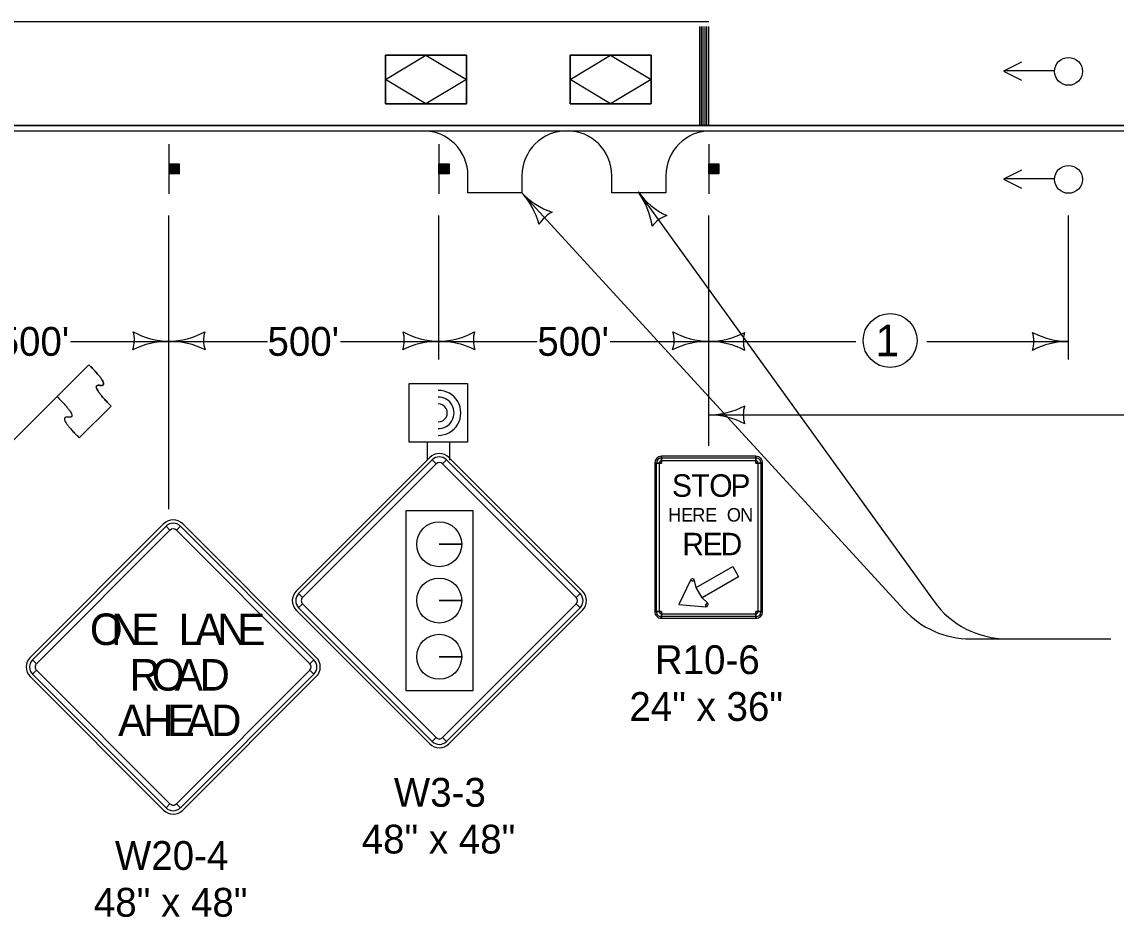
# Model space of a CAD drawing. Extents: x -2134934 to -2127057, y -2139046 to -2137036.
# Drawn here: x -2134616 to -2134008, y -2138105 to -2137608 of the extents above; entities that cross this region are included whole.
import ezdxf

# ---------------------------------------------------------------- set-up
doc = ezdxf.new("R2010")
doc.units = 0
for name, color, linetype in [('Barrier', 7, 'Continuous'), ('BridgeSuperStructureExisting', 7, 'Continuous'), ('DsnShtPlotIdentification', 7, 'Continuous'), ('DsnShtPlotShape', 7, 'Continuous'), ('dsnTextFinalPlan', 7, 'Continuous'), ('TC_Barrier', 7, 'Continuous')]:
    doc.layers.add(name, color=color, linetype=linetype)

msp = doc.modelspace()

# ---------------------------------------------------------------- linework, layer by layer
at = {"layer": 'Barrier'}
for p, q in [((-2134636.31, -2137855.42), (-2134578.99, -2137798.11)), ((-2134578.99, -2137798.11), (-2134596.67, -2137815.79)), ((-2134584.29, -2137838.78), (-2134566.61, -2137821.1)), ((-2134389.44, -2137849.65), (-2134463.68, -2137923.9)), ((-2134388.11, -2137850.98), (-2134385.9, -2137853.19)), ((-2134382.37, -2137853.19), (-2134380.16, -2137850.98)), ((-2134304.59, -2137923.9), (-2134378.83, -2137849.65)), ((-2134264.44, -2137852.75), (-2134260.69, -2137852.75)), ((-2134263.5, -2137852.75), (-2134261.94, -2137852.75)), ((-2134260.69, -2137852.75), (-2134260.69, -2137849)), ((-2134260.69, -2137851.5), (-2134260.69, -2137849.93)), ((-2134208.19, -2137849), (-2134208.19, -2137852.75)), ((-2134208.19, -2137849.93), (-2134208.19, -2137851.5)), ((-2134208.19, -2137852.75), (-2134204.44, -2137852.75)), ((-2134206.94, -2137852.75), (-2134205.38, -2137852.75)), ((-2134537.4, -2137886.48), (-2134611.65, -2137960.72)), ((-2134536.08, -2137887.8), (-2134533.87, -2137890.01)), ((-2134530.33, -2137890.01), (-2134528.12, -2137887.8)), ((-2134452.55, -2137960.72), (-2134526.8, -2137886.48)), ((-2134371.73, -2137897.87), (-2134384.23, -2137897.87)), ((-2134384.23, -2137897.87), (-2134371.73, -2137897.87)), ((-2134244.58, -2137917.73), (-2134243.48, -2137918.31)), ((-2134243.48, -2137918.31), (-2134242.26, -2137918.04)), ((-2134460.15, -2137927.43), (-2134462.36, -2137925.22)), ((-2134305.91, -2137925.22), (-2134308.12, -2137927.43)), ((-2134462.36, -2137933.18), (-2134460.15, -2137930.97)), ((-2134371.73, -2137929.12), (-2134384.23, -2137929.12)), ((-2134384.23, -2137929.12), (-2134371.73, -2137929.12)), ((-2134308.12, -2137930.97), (-2134305.91, -2137933.18)), ((-2134235.98, -2137931.3), (-2134236.03, -2137932.55)), ((-2134235.13, -2137930.38), (-2134235.98, -2137931.3)), ((-2134463.68, -2137934.5), (-2134389.44, -2138008.75)), ((-2134378.83, -2138008.75), (-2134304.59, -2137934.5)), ((-2134260.69, -2137935.24), (-2134264.44, -2137935.24)), ((-2134261.94, -2137935.24), (-2134263.5, -2137935.24)), ((-2134260.69, -2137938.99), (-2134260.69, -2137935.24)), ((-2134260.69, -2137938.06), (-2134260.69, -2137936.49)), ((-2134204.44, -2137935.24), (-2134208.19, -2137935.24)), ((-2134208.19, -2137935.24), (-2134208.19, -2137938.99)), ((-2134208.19, -2137936.49), (-2134208.19, -2137938.06)), ((-2134205.38, -2137935.24), (-2134206.94, -2137935.24)), ((-2134608.11, -2137964.26), (-2134610.32, -2137962.05)), ((-2134453.88, -2137962.05), (-2134456.08, -2137964.26)), ((-2134371.73, -2137960.37), (-2134384.23, -2137960.37)), ((-2134384.23, -2137960.37), (-2134371.73, -2137960.37)), ((-2134610.32, -2137970.01), (-2134608.11, -2137967.8)), ((-2134456.08, -2137967.8), (-2134453.88, -2137970.01)), ((-2134611.65, -2137971.33), (-2134537.4, -2138045.58)), ((-2134526.8, -2138045.58), (-2134452.55, -2137971.33)), ((-2134385.9, -2138005.21), (-2134388.11, -2138007.42)), ((-2134380.16, -2138007.42), (-2134382.37, -2138005.21)), ((-2134533.87, -2138042.04), (-2134536.08, -2138044.25)), ((-2134528.12, -2138044.25), (-2134530.33, -2138042.04))]:
    msp.add_line(p, q, dxfattribs=at)
for points in [[(-2134388.11, -2137850.98), (-2134462.36, -2137925.22), (-2134460.15, -2137927.43), (-2134385.9, -2137853.19), (-2134388.11, -2137850.98)], [(-2134305.91, -2137925.22), (-2134380.16, -2137850.98), (-2134382.37, -2137853.19), (-2134308.12, -2137927.43), (-2134305.91, -2137925.22)], [(-2134260.69, -2137938.99), (-2134208.19, -2137938.99), (-2134208.19, -2137935.24), (-2134204.44, -2137935.24), (-2134204.44, -2137852.75), (-2134208.19, -2137852.75), (-2134208.19, -2137849), (-2134260.69, -2137849), (-2134260.69, -2137852.75), (-2134264.44, -2137852.75), (-2134264.44, -2137935.24), (-2134260.69, -2137935.24), (-2134260.69, -2137938.99)], [(-2134261.94, -2137852.75), (-2134261.94, -2137935.24), (-2134263.5, -2137935.24), (-2134263.5, -2137852.75), (-2134261.94, -2137852.75)], [(-2134208.19, -2137851.5), (-2134260.69, -2137851.5), (-2134260.69, -2137849.93), (-2134208.19, -2137849.93), (-2134208.19, -2137851.5)], [(-2134206.94, -2137935.24), (-2134206.94, -2137852.75), (-2134205.38, -2137852.75), (-2134205.38, -2137935.24), (-2134206.94, -2137935.24)], [(-2134365.4, -2137879.26), (-2134402.87, -2137879.26), (-2134402.87, -2137979.15), (-2134365.4, -2137979.15), (-2134365.4, -2137879.26)], [(-2134536.08, -2137887.8), (-2134610.32, -2137962.05), (-2134608.11, -2137964.26), (-2134533.87, -2137890.01), (-2134536.08, -2137887.8)], [(-2134453.88, -2137962.05), (-2134528.12, -2137887.8), (-2134530.33, -2137890.01), (-2134456.08, -2137964.26), (-2134453.88, -2137962.05)], [(-2134221.07, -2137910.24), (-2134217.79, -2137915.93), (-2134238.1, -2137927.65), (-2134241.38, -2137921.97), (-2134221.07, -2137910.24)], [(-2134251.09, -2137931.37), (-2134236.03, -2137932.55), (-2134235.98, -2137931.3), (-2134235.13, -2137930.38), (-2134238.1, -2137927.65), (-2134241.38, -2137921.97), (-2134242.26, -2137918.04), (-2134243.48, -2137918.31), (-2134244.58, -2137917.73), (-2134251.09, -2137931.37)], [(-2134462.36, -2137933.18), (-2134388.11, -2138007.42), (-2134385.9, -2138005.21), (-2134460.15, -2137930.97), (-2134462.36, -2137933.18)], [(-2134380.16, -2138007.42), (-2134305.91, -2137933.18), (-2134308.12, -2137930.97), (-2134382.37, -2138005.21), (-2134380.16, -2138007.42)], [(-2134260.69, -2137936.49), (-2134208.19, -2137936.49), (-2134208.19, -2137938.06), (-2134260.69, -2137938.06), (-2134260.69, -2137936.49)], [(-2134610.32, -2137970.01), (-2134536.08, -2138044.25), (-2134533.87, -2138042.04), (-2134608.11, -2137967.8), (-2134610.32, -2137970.01)], [(-2134528.12, -2138044.25), (-2134453.88, -2137970.01), (-2134456.08, -2137967.8), (-2134530.33, -2138042.04), (-2134528.12, -2138044.25)]]:
    msp.add_lwpolyline(points, close=True, dxfattribs=at)
for centre in [(-2134384.23, -2137897.87), (-2134384.23, -2137929.12), (-2134384.23, -2137960.37)]:
    msp.add_circle(centre, 12.5, dxfattribs=at)
for centre, radius, start, end in [((-2134384.14, -2137854.96), 7.5, 44.99999, 134.99974), ((-2134384.14, -2137854.96), 5.62, 44.99999, 134.99974), ((-2134384.14, -2137854.96), 2.5, 44.99999, 134.99974), ((-2134260.69, -2137852.75), 3.75, 90.00021, 179.99985), ((-2134260.69, -2137852.75), 2.81, 90.00021, 179.99985), ((-2134260.69, -2137852.75), 1.25, 90.00021, 179.99985), ((-2134208.19, -2137852.75), 3.75, 0, 90.00021), ((-2134208.19, -2137852.75), 2.81, 0, 90.00021), ((-2134208.19, -2137852.75), 1.25, 0, 90.00021), ((-2134532.1, -2137891.78), 7.5, 44.99999, 134.99974), ((-2134532.1, -2137891.78), 5.62, 44.99999, 134.99974), ((-2134532.1, -2137891.78), 2.5, 44.99999, 134.99974), ((-2134243.48, -2137918.31), 1.25, 12.62232, 152.27557), ((-2134458.38, -2137929.2), 7.5, 134.99974, 224.99995), ((-2134458.38, -2137929.2), 5.62, 134.99974, 224.99995), ((-2134309.89, -2137929.2), 5.62, 315.00016, 44.9998), ((-2134309.89, -2137929.2), 7.5, 315.00016, 44.9998), ((-2134458.38, -2137929.2), 2.5, 134.99974, 224.99995), ((-2134309.89, -2137929.2), 2.5, 315.00016, 44.9998), ((-2134235.98, -2137931.3), 1.25, 267.72427, 47.37758), ((-2134260.69, -2137935.24), 3.75, 179.99985, 270.00006), ((-2134260.69, -2137935.24), 2.81, 179.99985, 270.00006), ((-2134260.69, -2137935.24), 1.25, 179.99985, 270.00006), ((-2134208.19, -2137935.24), 3.75, 270.00006, 0.00027), ((-2134208.19, -2137935.24), 2.81, 270.00006, 0.00027), ((-2134208.19, -2137935.24), 1.25, 270.00006, 0.00027), ((-2134606.34, -2137966.03), 7.5, 134.99974, 224.99995), ((-2134606.34, -2137966.03), 5.62, 134.99974, 224.99995), ((-2134457.85, -2137966.03), 5.62, 315.00016, 44.9998), ((-2134457.85, -2137966.03), 7.5, 315.00016, 44.9998), ((-2134606.34, -2137966.03), 2.5, 134.99974, 224.99995), ((-2134457.85, -2137966.03), 2.5, 315.00016, 44.9998), ((-2134384.14, -2138003.45), 7.5, 224.99995, 315.00016), ((-2134384.14, -2138003.45), 5.62, 224.99995, 315.00016), ((-2134384.14, -2138003.45), 2.5, 224.99995, 315.00016), ((-2134532.1, -2138040.27), 7.5, 224.99995, 315.00016), ((-2134532.1, -2138040.27), 5.62, 224.99995, 315.00016), ((-2134532.1, -2138040.27), 2.5, 224.99995, 315.00016)]:
    msp.add_arc(centre, radius, start, end, dxfattribs=at)
for points in [[(-2134566.61, -2137821.1), (-2134578.99, -2137808.72), (-2134566.61, -2137810.49), (-2134578.99, -2137798.11)], [(-2134596.67, -2137815.79), (-2134584.29, -2137828.17), (-2134596.66, -2137826.4), (-2134584.29, -2137838.78)]]:
    msp.add_open_spline(points, degree=2, dxfattribs=at)
at = {"layer": 'BridgeSuperStructureExisting'}
for p, q in [((-2134239.44, -2137665.16), (-2134239.44, -2137610.16)), ((-2134238.44, -2137665.16), (-2134238.44, -2137610.16)), ((-2134237.44, -2137665.16), (-2134237.44, -2137610.16)), ((-2134236.44, -2137665.16), (-2134236.44, -2137610.16)), ((-2134235.44, -2137665.16), (-2134235.44, -2137610.16)), ((-2134234.44, -2137665.16), (-2134234.44, -2137610.16)), ((-2134414.12, -2137653.13), (-2134414.12, -2137626.13)), ((-2134414.12, -2137626.13), (-2134369.12, -2137626.13)), ((-2134414.12, -2137653.13), (-2134414.12, -2137626.13)), ((-2134414.12, -2137626.13), (-2134369.12, -2137626.13)), ((-2134369.12, -2137626.13), (-2134414.12, -2137626.13)), ((-2134414.12, -2137626.13), (-2134414.12, -2137653.13)), ((-2134369.12, -2137653.13), (-2134369.12, -2137626.13)), ((-2134369.12, -2137626.13), (-2134369.12, -2137653.13)), ((-2134369.12, -2137653.13), (-2134369.12, -2137626.13)), ((-2134311.44, -2137653.13), (-2134311.44, -2137626.13)), ((-2134311.44, -2137626.13), (-2134266.44, -2137626.13)), ((-2134311.44, -2137653.13), (-2134311.44, -2137626.13)), ((-2134311.44, -2137626.13), (-2134266.44, -2137626.13)), ((-2134266.44, -2137626.13), (-2134311.44, -2137626.13)), ((-2134311.44, -2137626.13), (-2134311.44, -2137653.13)), ((-2134266.44, -2137653.13), (-2134266.44, -2137626.13)), ((-2134266.44, -2137626.13), (-2134266.44, -2137653.13)), ((-2134266.44, -2137653.13), (-2134266.44, -2137626.13)), ((-2134042.18, -2137634.79), (-2134070.12, -2137634.79)), ((-2134414.12, -2137653.13), (-2134369.12, -2137653.13)), ((-2134369.12, -2137653.13), (-2134414.12, -2137653.13)), ((-2134414.12, -2137653.13), (-2134369.12, -2137653.13)), ((-2134311.44, -2137653.13), (-2134266.44, -2137653.13)), ((-2134266.44, -2137653.13), (-2134311.44, -2137653.13)), ((-2134311.44, -2137653.13), (-2134266.44, -2137653.13)), ((-2134884.44, -2137665.16), (-2133384.44, -2137665.16)), ((-2134393.26, -2137668.16), (-2134313.26, -2137668.16)), ((-2134313.26, -2137668.16), (-2134233.26, -2137668.16)), ((-2134534.44, -2137675.66), (-2134534.44, -2137703.16)), ((-2134384.44, -2137675.66), (-2134384.44, -2137703.16)), ((-2134234.44, -2137675.66), (-2134234.44, -2137703.16)), ((-2134534.03, -2137692.11), (-2134534.03, -2137686.52)), ((-2134533.75, -2137686.52), (-2134533.75, -2137692.11)), ((-2134533.48, -2137692.11), (-2134533.48, -2137686.52)), ((-2134533.22, -2137686.52), (-2134533.22, -2137692.11)), ((-2134533, -2137692.11), (-2134533, -2137686.52)), ((-2134532.79, -2137686.52), (-2134532.79, -2137692.11)), ((-2134532.45, -2137692.11), (-2134532.45, -2137686.52)), ((-2134532.19, -2137686.52), (-2134532.19, -2137692.11)), ((-2134531.97, -2137692.11), (-2134531.98, -2137686.52)), ((-2134531.65, -2137686.52), (-2134531.65, -2137692.11)), ((-2134531.27, -2137692.11), (-2134531.27, -2137686.52)), ((-2134530.84, -2137686.52), (-2134530.84, -2137692.11)), ((-2134530.62, -2137692.11), (-2134530.63, -2137686.52)), ((-2134530.2, -2137686.52), (-2134530.18, -2137692.11)), ((-2134529.98, -2137692.11), (-2134529.98, -2137686.52)), ((-2134529.66, -2137686.52), (-2134529.66, -2137692.11)), ((-2134529.43, -2137692.11), (-2134529.43, -2137686.52)), ((-2134529.12, -2137686.52), (-2134529.12, -2137692.11)), ((-2134384.03, -2137692.11), (-2134384.03, -2137686.52)), ((-2134383.75, -2137686.52), (-2134383.75, -2137692.11)), ((-2134383.48, -2137692.11), (-2134383.48, -2137686.52)), ((-2134383.22, -2137686.52), (-2134383.22, -2137692.11)), ((-2134383, -2137692.11), (-2134383, -2137686.52)), ((-2134382.79, -2137686.52), (-2134382.79, -2137692.11)), ((-2134382.45, -2137692.11), (-2134382.45, -2137686.52)), ((-2134382.19, -2137686.52), (-2134382.19, -2137692.11)), ((-2134381.97, -2137692.11), (-2134381.98, -2137686.52)), ((-2134381.65, -2137686.52), (-2134381.65, -2137692.11)), ((-2134381.27, -2137692.11), (-2134381.27, -2137686.52)), ((-2134380.84, -2137686.52), (-2134380.84, -2137692.11)), ((-2134380.62, -2137692.11), (-2134380.63, -2137686.52)), ((-2134380.2, -2137686.52), (-2134380.18, -2137692.11)), ((-2134379.98, -2137692.11), (-2134379.98, -2137686.52)), ((-2134379.66, -2137686.52), (-2134379.66, -2137692.11)), ((-2134379.43, -2137692.11), (-2134379.43, -2137686.52)), ((-2134379.12, -2137686.52), (-2134379.12, -2137692.11)), ((-2134234.03, -2137692.11), (-2134234.03, -2137686.52)), ((-2134233.75, -2137686.52), (-2134233.75, -2137692.11)), ((-2134233.49, -2137692.11), (-2134233.49, -2137686.52)), ((-2134233.22, -2137686.52), (-2134233.22, -2137692.11)), ((-2134233, -2137692.11), (-2134233, -2137686.52)), ((-2134232.79, -2137686.52), (-2134232.79, -2137692.11)), ((-2134232.45, -2137692.11), (-2134232.45, -2137686.52)), ((-2134232.19, -2137686.52), (-2134232.19, -2137692.11)), ((-2134231.97, -2137692.11), (-2134231.99, -2137686.52)), ((-2134231.65, -2137686.52), (-2134231.65, -2137692.11)), ((-2134231.27, -2137692.11), (-2134231.27, -2137686.52)), ((-2134230.84, -2137686.52), (-2134230.84, -2137692.11)), ((-2134230.62, -2137692.11), (-2134230.64, -2137686.52)), ((-2134230.2, -2137686.52), (-2134230.19, -2137692.11)), ((-2134229.98, -2137692.11), (-2134229.98, -2137686.52)), ((-2134229.66, -2137686.52), (-2134229.66, -2137692.11)), ((-2134229.44, -2137692.11), (-2134229.44, -2137686.52)), ((-2134229.12, -2137686.52), (-2134229.12, -2137692.11)), ((-2134042.18, -2137694.79), (-2134070.12, -2137694.79)), ((-2134338.7, -2137702.19), (-2134125.8, -2137934.23)), ((-2134273.64, -2137702.14), (-2134109.13, -2137929.72)), ((-2134534.44, -2137878.33), (-2134534.44, -2137715.16)), ((-2134384.44, -2137795.16), (-2134384.44, -2137715.16)), ((-2134234.44, -2137843.11), (-2134234.44, -2137715.16)), ((-2134034.44, -2137795.16), (-2134034.44, -2137715.16)), ((-2134589.19, -2137785.16), (-2134534.44, -2137785.16)), ((-2134534.44, -2137785.16), (-2134479.69, -2137785.16)), ((-2134439.19, -2137785.16), (-2134384.44, -2137785.16)), ((-2134384.44, -2137785.16), (-2134329.69, -2137785.16)), ((-2134289.19, -2137785.16), (-2134234.44, -2137785.16)), ((-2134234.44, -2137785.16), (-2134152.68, -2137785.16)), ((-2134113.22, -2137785.16), (-2134034.44, -2137785.16)), ((-2134234.44, -2137825.98), (-2133930.88, -2137825.98)), ((-2134390.98, -2137841.1), (-2134390.98, -2137851.1)), ((-2134378.48, -2137841.1), (-2134378.48, -2137851.1)), ((-2134088.96, -2137950.42), (-2134010.82, -2137950.42))]:
    msp.add_line(p, q, dxfattribs=at)
for points in [[(-2134060.49, -2137629.98), (-2134070.49, -2137634.98), (-2134060.49, -2137639.98)], [(-2134338.26, -2137693.16), (-2134338.26, -2137702.65), (-2134368.26, -2137702.65), (-2134368.26, -2137693.16)], [(-2134258.26, -2137693.16), (-2134258.26, -2137702.65), (-2134288.26, -2137702.65), (-2134288.26, -2137693.16)], [(-2134060.49, -2137689.98), (-2134070.49, -2137694.98), (-2134060.49, -2137699.98)]]:
    msp.add_lwpolyline(points, dxfattribs=at)
for points in [[(-2134534.35, -2137692.11), (-2134534.35, -2137686.48), (-2134528.72, -2137686.48), (-2134528.72, -2137692.11)], [(-2134384.35, -2137692.11), (-2134384.35, -2137686.48), (-2134378.72, -2137686.48), (-2134378.72, -2137692.11)], [(-2134234.35, -2137692.11), (-2134234.35, -2137686.48), (-2134228.72, -2137686.48), (-2134228.72, -2137692.11)], [(-2134400.98, -2137841.1), (-2134400.98, -2137808.6), (-2134368.48, -2137808.6), (-2134368.48, -2137841.1)]]:
    msp.add_lwpolyline(points, close=True, dxfattribs=at)
for centre, radius in [((-2134034.44, -2137635.16), 7.74), ((-2134034.44, -2137695.16), 7.74), ((-2134133.59, -2137784.66), 15)]:
    msp.add_circle(centre, radius, dxfattribs=at)
for centre, radius, start, end in [((-2134393.26, -2137693.16), 25, 0, 90), ((-2134313.26, -2137693.16), 25, 90, 180), ((-2134313.26, -2137693.16), 25, 0, 90), ((-2134233.26, -2137693.16), 25, 90, 180), ((-2134570.06, -2137784.54), 16.42, 341.26665, 16.73335), ((-2134533.69, -2137742.67), 42.5, 240.92751, 268.9824), ((-2134535.2, -2137742.67), 42.5, 271.0176, 299.07249), ((-2134498.82, -2137784.54), 16.42, 163.26665, 198.73335), ((-2134420.06, -2137784.54), 16.42, 341.26665, 16.73335), ((-2134383.69, -2137742.67), 42.5, 240.92751, 268.9824), ((-2134385.2, -2137742.67), 42.5, 271.0176, 299.07249), ((-2134348.82, -2137784.54), 16.42, 163.26665, 198.73335), ((-2134270.06, -2137784.54), 16.42, 341.26665, 16.73335), ((-2134233.69, -2137742.67), 42.5, 240.92751, 268.9824), ((-2134535.17, -2137827.65), 42.5, 89.0176, 117.07249), ((-2134533.71, -2137827.65), 42.5, 62.92751, 90.9824), ((-2134385.17, -2137827.65), 42.5, 89.0176, 117.07249), ((-2134383.71, -2137827.65), 42.5, 62.92751, 90.9824), ((-2134235.17, -2137827.65), 42.5, 89.0176, 117.07249), ((-2134234.44, -2137742.66), 42.5, 270, 298.07249), ((-2134234.44, -2137827.66), 42.5, 61.92751, 90), ((-2134198.81, -2137785.16), 16.42, 162.26665, 197.73335), ((-2134070.08, -2137785.16), 16.42, 342.26665, 17.73335), ((-2134034.44, -2137742.66), 42.5, 241.92751, 270), ((-2134034.44, -2137827.66), 42.5, 90, 118.07249), ((-2134384.72, -2137824.87), 12.5, 269.40414, 90.54446), ((-2134384.72, -2137824.87), 12.5, 269.40414, 90.54446), ((-2134384.72, -2137824.87), 8.75, 269.40414, 90.54446), ((-2134384.72, -2137824.87), 5, 269.40414, 90.54446), ((-2134068.61, -2137900.42), 50, 215.86205, 270), ((-2134088.96, -2137900.42), 50, 222.53616, 270)]:
    msp.add_arc(centre, radius, start, end, dxfattribs=at)
at = {"layer": 'DsnShtPlotIdentification'}
for p, q in [((-2134234.44, -2137607.66), (-2134886.94, -2137607.66)), ((-2134884.44, -2137665.16), (-2133384.44, -2137665.16)), ((-2134884.44, -2137665.16), (-2133384.44, -2137665.16)), ((-2134239.44, -2137665.16), (-2134884.44, -2137665.16)), ((-2134884.44, -2137668.16), (-2133384.44, -2137668.16)), ((-2134884.44, -2137668.16), (-2133384.44, -2137668.16)), ((-2134238.44, -2137665.16), (-2134239.44, -2137665.16)), ((-2134237.44, -2137665.16), (-2134238.44, -2137665.16)), ((-2134236.44, -2137665.16), (-2134237.44, -2137665.16)), ((-2133384.44, -2137665.16), (-2134234.44, -2137665.16))]:
    msp.add_line(p, q, dxfattribs=at)
msp.add_lwpolyline([(-2134234.44, -2137665.16), (-2134235.44, -2137665.16), (-2134236.44, -2137665.16)], dxfattribs=at)
at = {"layer": 'DsnShtPlotShape'}
for centre, radius, start, end in [((-2134307.6, -2137673.22), 42.5, 222.97313, 251.04562), ((-2134369.79, -2137731.16), 42.5, 14.90064, 42.97313), ((-2134239.39, -2137676.98), 42.5, 216.29902, 244.37151), ((-2134307.89, -2137727.3), 42.5, 8.22653, 36.29902), ((-2134314.41, -2137728.26), 16.42, 115.23978, 150.70648), ((-2134252.54, -2137730.86), 16.42, 108.56567, 144.03237), ((-2134234.44, -2137783.48), 42.5, 270, 298.07249), ((-2134198.81, -2137825.98), 16.42, 162.26665, 197.73335), ((-2134234.44, -2137868.48), 42.5, 61.92751, 90)]:
    msp.add_arc(centre, radius, start, end, dxfattribs=at)
at = {"layer": 'dsnTextFinalPlan'}
for points in [[(-2134414.12, -2137639.63), (-2134391.62, -2137626.13), (-2134369.12, -2137639.63), (-2134391.62, -2137653.13)], [(-2134311.44, -2137639.63), (-2134288.94, -2137626.13), (-2134266.44, -2137639.63), (-2134288.94, -2137653.13)]]:
    msp.add_lwpolyline(points, close=True, dxfattribs=at)
at = {"layer": 'TC_Barrier'}
msp.add_line((-2134566.61, -2137821.1), (-2134584.29, -2137838.78), dxfattribs=at)
for points in [[(-2134578.99, -2137798.11), (-2134566.61, -2137810.49), (-2134578.99, -2137808.72), (-2134566.61, -2137821.1)], [(-2134596.67, -2137815.79), (-2134584.29, -2137828.17), (-2134596.66, -2137826.4), (-2134584.29, -2137838.78)]]:
    msp.add_open_spline(points, degree=2, dxfattribs=at)

# ---------------------------------------------------------------- texts
at = {"layer": 'Barrier'}
for s, height, p in [('S', 12.5, (-2134254.89, -2137871.5)), ('O', 12.5, (-2134234.14, -2137871.5)), ('T', 12.5, (-2134244.13, -2137871.5)), ('P', 12.5, (-2134222.39, -2137871.5)), ('H', 7.5, (-2134256.97, -2137885.25)), ('E', 7.5, (-2134249.82, -2137885.25)), ('R', 7.5, (-2134243.56, -2137885.25)), ('E', 7.5, (-2134236.41, -2137885.25)), ('O', 7.5, (-2134224.34, -2137885.25)), ('N', 7.5, (-2134216.96, -2137885.25)), ('R', 12.5, (-2134249.13, -2137904)), ('E', 12.5, (-2134237.8, -2137904)), ('D', 12.5, (-2134227.84, -2137904)), ('O', 17.5, (-2134578.38, -2137953.84)), ('N', 17.5, (-2134566.61, -2137953.84)), ('E', 17.5, (-2134555.38, -2137953.84)), ('L', 17.5, (-2134529.13, -2137953.84)), ('A', 17.5, (-2134519.93, -2137953.84)), ('N', 17.5, (-2134507.67, -2137953.84)), ('E', 17.5, (-2134496.44, -2137953.84)), ('R10-6', 16, (-2134264.37, -2137969.99)), ('R', 17.5, (-2134556.28, -2137979.15)), ('O', 17.5, (-2134543.99, -2137979.15)), ('A', 17.5, (-2134531.15, -2137979.15)), ('D', 17.5, (-2134517.49, -2137979.15)), ('24" x 36"', 16, (-2134278.51, -2137995.99)), ('A', 17.5, (-2134562.71, -2138004.47)), ('H', 17.5, (-2134548.85, -2138004.47)), ('E', 17.5, (-2134535.63, -2138004.47)), ('A', 17.5, (-2134524.92, -2138004.47)), ('D', 17.5, (-2134511.05, -2138004.47)), ('W3-3', 16, (-2134409.43, -2138043.67)), ('48" x 48"', 16, (-2134427.31, -2138069.67)), ('W20-4', 16, (-2134564.47, -2138078.77)), ('48" x 48"', 16, (-2134576.17, -2138104.77))]:
    msp.add_text(s, height=height, dxfattribs=at).set_placement(p)
at = {"layer": 'BridgeSuperStructureExisting'}
for s, height, p in [("500'", 16, (-2134629.69, -2137793.16)), ("500'", 16, (-2134479.69, -2137793.16)), ("500'", 16, (-2134329.69, -2137793.16)), ('1', 17.5, (-2134141.65, -2137793.41))]:
    msp.add_text(s, height=height, dxfattribs=at).set_placement(p)

doc.saveas('drawing.dxf')
